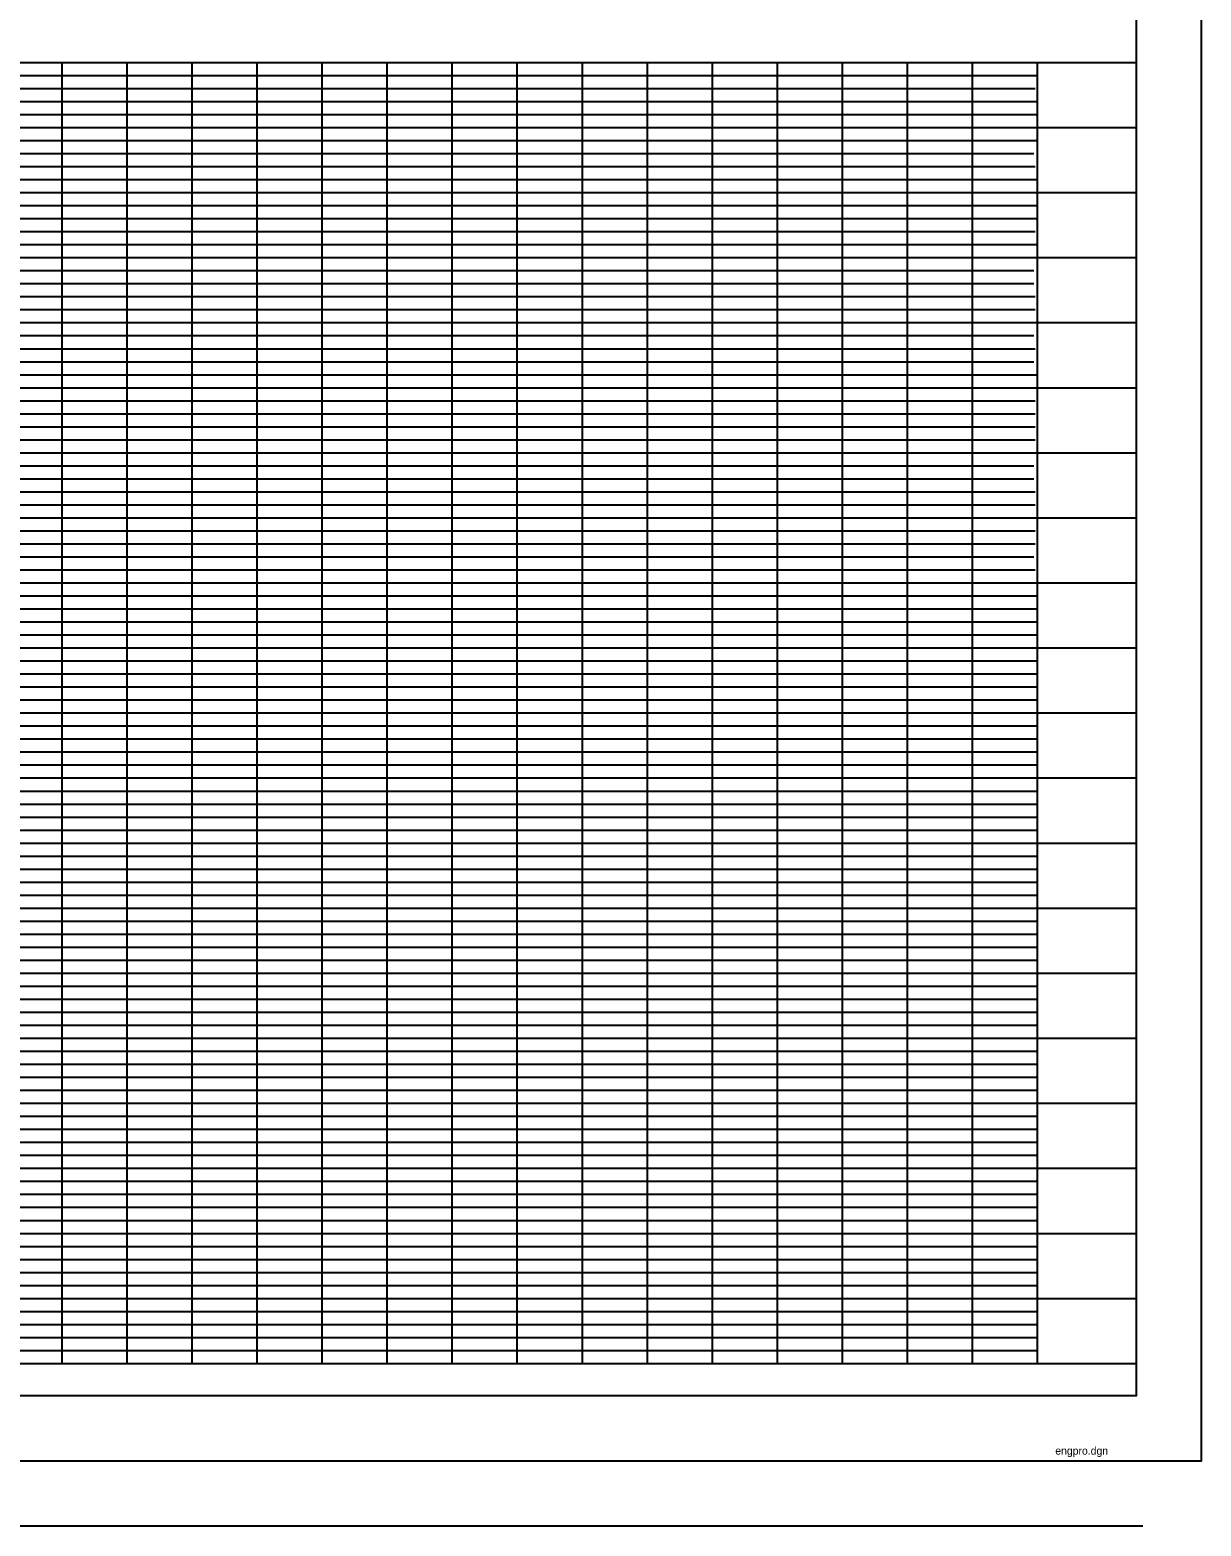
# Model space of a CAD drawing. Extents: x -183 to 1613, y -563 to 588.
# Drawn here: x 1163 to 1613, y -563 to 12 of the extents above; entities that cross this region are included whole.
import ezdxf

# ---------------------------------------------------------------- set-up
doc = ezdxf.new("R2010")
doc.units = 0
for name, color, linetype in [('RD_SHT_Bndy', 7, 'Continuous'), ('RD_SHT_Iplotshp', 7, 'Continuous'), ('RD_SHT_MjGrid', 7, 'Continuous'), ('RD_SHT_MnGrid', 7, 'Continuous'), ('RD_SHT_SubGrid', 7, 'Continuous'), ('RD_SHT_TX', 7, 'Continuous')]:
    doc.layers.add(name, color=color, linetype=linetype)

msp = doc.modelspace()

# ---------------------------------------------------------------- linework, layer by layer
at = {"layer": 'RD_SHT_Bndy'}
for p, q in [((-87, 0), (1588, 0)), ((1550, 0), (1550, -500)), ((-87, -500), (1588, -500)), ((1590.65, -537.5), (-169.35, -537.5)), ((1590.65, -562.5), (-169.35, -562.5))]:
    msp.add_line(p, q, dxfattribs=at)
msp.add_lwpolyline([(-87, 537.5), (1588, 537.5), (1588, -512.5), (-87, -512.5)], close=True, dxfattribs=at)
at = {"layer": 'RD_SHT_Iplotshp'}
msp.add_lwpolyline([(-182.9, 562.5), (1613, 562.5), (1613, -537.5), (-182.9, -537.5)], close=True, dxfattribs=at)
at = {"layer": 'RD_SHT_MjGrid'}
for p, q in [((1200, 0), (1200, -500)), ((1250, 0), (1250, -500)), ((1300, 0), (1300, -500)), ((1350, 0), (1350, -500)), ((1400, 0), (1400, -500)), ((1450, 0), (1450, -500)), ((1500, 0), (1500, -500)), ((-87, -50), (1588, -50)), ((-87, -100), (1588, -100)), ((-87, -150), (1588, -150)), ((-87, -200), (1588, -200)), ((-87, -250), (1588, -250)), ((-87, -300), (1588, -300)), ((-87, -350), (1588, -350)), ((-87, -400), (1588, -400)), ((-87, -450), (1588, -450))]:
    msp.add_line(p, q, dxfattribs=at)
at = {"layer": 'RD_SHT_MnGrid'}
for p, q in [((1175, 0), (1175, -500)), ((1225, 0), (1225, -500)), ((1275, 0), (1275, -500)), ((1325, 0), (1325, -500)), ((1375, 0), (1375, -500)), ((1425, 0), (1425, -500)), ((1475, 0), (1475, -500)), ((1525, 0), (1525, -500)), ((-87, -25), (1588, -25)), ((-87, -75), (1588, -75)), ((-87, -125), (1588, -125)), ((-87, -175), (1588, -175)), ((-87, -225), (1588, -225)), ((-87, -275), (1588, -275)), ((-87, -325), (1588, -325)), ((-87, -375), (1588, -375)), ((-87, -425), (1588, -425)), ((-87, -475), (1588, -475))]:
    msp.add_line(p, q, dxfattribs=at)
at = {"layer": 'RD_SHT_SubGrid'}
for p, q in [((-49.95, -5), (1549.8, -5)), ((-49.95, -10), (1549.25, -10)), ((-49.95, -15), (1549.8, -15)), ((-49.9, -20), (1549.8, -20)), ((-49.95, -30), (1549.8, -30)), ((-49.95, -35), (1548.75, -35)), ((-49.95, -40), (1549.25, -40)), ((-49.95, -45), (1549.8, -45)), ((-49.95, -55), (1549.8, -55)), ((-49.95, -60), (1549.8, -60)), ((-49.95, -65), (1549.25, -65)), ((-49.95, -70), (1549.8, -70)), ((-49.95, -80), (1548.75, -80)), ((-49.95, -85), (1548.75, -85)), ((-49.95, -90), (1549.25, -90)), ((-49.95, -95), (1549.25, -95)), ((-49.95, -105), (1548.75, -105)), ((-49.95, -110), (1549.25, -110)), ((-49.95, -115), (1548.75, -115)), ((-49.9, -120), (1549.8, -120)), ((-49.95, -130), (1549.25, -130)), ((-49.95, -135), (1549.25, -135)), ((-49.95, -140), (1549.25, -140)), ((-49.95, -145), (1549.25, -145)), ((-49.85, -155), (1548.75, -155)), ((-49.85, -160), (1548.75, -160)), ((-49.9, -165), (1549.25, -165)), ((-49.9, -170), (1549.25, -170)), ((-49.95, -180), (1549.25, -180)), ((-49.95, -185), (1549.25, -185)), ((-49.95, -190), (1548.75, -190)), ((-49.95, -195), (1549.25, -195)), ((-49.95, -195), (1549.25, -195)), ((-49.95, -205), (1549.8, -205)), ((-49.95, -210), (1549.8, -210)), ((-49.95, -215), (1549.8, -215)), ((-49.95, -220), (1549.8, -220)), ((-49.95, -230), (1549.8, -230)), ((-49.95, -235), (1549.8, -235)), ((-49.95, -240), (1549.8, -240)), ((-49.95, -245), (1549.8, -245)), ((-49.95, -255), (1549.85, -255)), ((-49.95, -260), (1549.85, -260)), ((-49.95, -265), (1549.85, -265)), ((-49.95, -270), (1549.85, -270)), ((-49.95, -280), (1549.85, -280)), ((-49.95, -285), (1549.85, -285)), ((-49.95, -290), (1549.85, -290)), ((-49.95, -295), (1549.85, -295)), ((-49.95, -305), (1549.85, -305)), ((-49.95, -310), (1549.85, -310)), ((-49.95, -315), (1549.85, -315)), ((-49.95, -320), (1549.85, -320)), ((-49.95, -330), (1549.85, -330)), ((-49.9, -330), (1549.85, -330)), ((-49.95, -335), (1549.85, -335)), ((-49.9, -340), (1549.6, -340)), ((-49.9, -345), (1549.6, -345)), ((-49.9, -355), (1549.8, -355)), ((-49.95, -360), (1549.95, -360)), ((-49.95, -365), (1549.95, -365)), ((-49.9, -370), (1549.95, -370)), ((-49.95, -380), (1549.95, -380)), ((-49.95, -385), (1549.95, -385)), ((-49.95, -390), (1549.95, -390)), ((-49.9, -395), (1549.95, -395)), ((-49.95, -405), (1549.95, -405)), ((-49.95, -410), (1549.95, -410)), ((-49.95, -415), (1549.95, -415)), ((-49.95, -420), (1549.85, -420)), ((-49.9, -430), (1549.6, -430)), ((-49.95, -435), (1549.85, -435)), ((-49.95, -440), (1549.85, -440)), ((-49.95, -445), (1549.85, -445)), ((-49.95, -460), (1549.85, -460)), ((-49.85, -455), (1549.85, -455)), ((-49.95, -465), (1549.85, -465)), ((-49.95, -470), (1549.85, -470)), ((-49.85, -480), (1549.85, -480)), ((-49.85, -485), (1549.85, -485)), ((-49.85, -490), (1549.85, -490)), ((-49.85, -495), (1549.85, -495))]:
    msp.add_line(p, q, dxfattribs=at)

# ---------------------------------------------------------------- texts
at = {"layer": 'RD_SHT_TX'}
msp.add_text('engpro.dgn', height=3, dxfattribs=at).set_placement((1556.95, -535.05))

doc.saveas('drawing.dxf')
